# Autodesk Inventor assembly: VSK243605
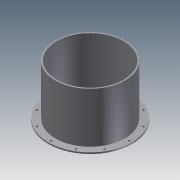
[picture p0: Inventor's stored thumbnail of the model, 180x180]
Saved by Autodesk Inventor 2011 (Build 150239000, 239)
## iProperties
Created: 2010-06
Part Number: VSK243605
Document SubType Name: Assembly
Designer: mklassen
OD: 24.000 in
THK: 0.500 in
SKVOFS: 6.000 in
SKLEN: 3.000 ft
Author: mklassen
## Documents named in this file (3)
- O:\cadd\tutorials\inventor 2011\iLogic\VSK243605.iam
- O:\cadd\tutorials\inventor 2011\iLogic\Skirt-01.ipt
- O:\cadd\tutorials\inventor 2011\iLogic\SkirtFlange-01.ipt
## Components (2 placed, 2 different names)
1. Skirt-01:1 — Flush:1, Flush:2, Flush:3
2. SkirtFlange-01:1 — Flush:4, Flush:5
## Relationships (5: Flush 5)
- Flush:1: Skirt-01:1
- Flush:2: Skirt-01:1
- Flush:3: Skirt-01:1
- Flush:4: SkirtFlange-01:1
- Flush:5: SkirtFlange-01:1
